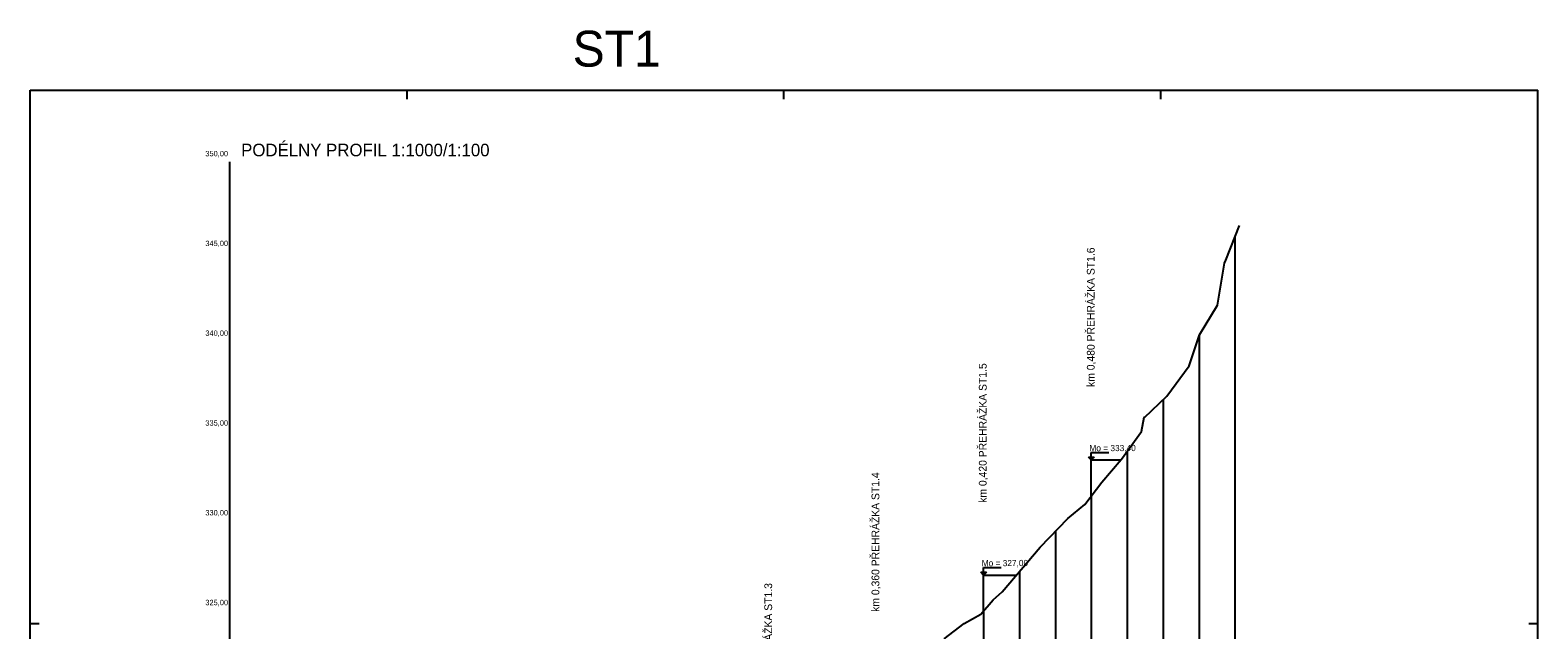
# Model space of a CAD drawing. Extents: x -500244 to -499404, y -1136557 to -1135632.
# Drawn here: x -500244 to -499404, y -1135966 to -1135632 of the extents above; entities that cross this region are included whole.
import ezdxf

# ---------------------------------------------------------------- set-up
doc = ezdxf.new("R2010")
doc.units = 0
for name, color, linetype in [('03_PC_NÁVRH_AS_H', 7, 'Continuous'), ('13', 7, 'Continuous'), ('28', 7, 'Continuous'), ('4', 7, 'Continuous'), ('56', 7, 'Continuous'), ('hraniceABH', 7, 'Continuous'), ('Vrstva 1', 7, 'Continuous'), ('Vrstva 4', 7, 'Continuous')]:
    doc.layers.add(name, color=color, linetype=linetype)

msp = doc.modelspace()

# ---------------------------------------------------------------- linework, layer by layer
for points in [[(-499734.44, -1135971.22), (-499723.25, -1135962.62), (-499723.22, -1135962.63), (-499714.02, -1135957.42), (-499714.02, -1135957.42), (-499707.14, -1135949.42), (-499707.14, -1135949.42), (-499702.11, -1135944.92), (-499702.11, -1135944.92), (-499702.11, -1135944.92), (-499694.61, -1135936.24), (-499680.87, -1135920.12), (-499680.87, -1135920.12), (-499665.52, -1135904.22), (-499665.52, -1135904.22), (-499656.1, -1135896.32), (-499656.1, -1135896.32), (-499646.62, -1135883.92), (-499646.62, -1135883.92), (-499646.61, -1135883.92), (-499635.77, -1135871.36), (-499635.66, -1135871), (-499624.55, -1135855.62), (-499624.55, -1135855.62), (-499623.08, -1135847.68), (-499622.93, -1135847.76), (-499622.8, -1135847.96), (-499622.79, -1135847.93), (-499610.45, -1135836.02), (-499610.45, -1135836.02), (-499597.89, -1135819.12), (-499597.89, -1135819.12), (-499592.27, -1135801.92), (-499592.27, -1135801.92), (-499582.12, -1135785.32), (-499582.12, -1135785.32), (-499578.28, -1135762.02), (-499577.46, -1135760.29), (-499569.89, -1135740.92)], [(-499572.45, -1135747.48), (-499572.45, -1136385.42), (-499572.45, -1136395.42), (-499572.45, -1136424.49)], [(-499592.45, -1135802.47), (-499592.45, -1136385.42), (-499592.45, -1136395.42), (-499592.45, -1136424.49)], [(-499612.45, -1135837.95), (-499612.45, -1136385.42), (-499612.45, -1136395.42), (-499612.45, -1136424.49)], [(-499632.45, -1135866.56), (-499632.45, -1136385.42), (-499632.45, -1136395.42), (-499632.45, -1136424.49)], [(-499652.45, -1135891.55), (-499652.45, -1136385.42), (-499652.45, -1136395.42), (-499652.45, -1136424.49)], [(-499672.45, -1135911.4), (-499672.45, -1136385.42), (-499672.45, -1136395.42), (-499672.45, -1136424.49)], [(-499692.45, -1135933.71), (-499692.45, -1136385.42), (-499692.45, -1136395.42), (-499692.45, -1136424.49)], [(-499712.45, -1135955.6), (-499712.45, -1136385.42), (-499712.45, -1136395.42), (-499712.45, -1136424.49)]]:
    msp.add_lwpolyline(points)
at = {"layer": '03_PC_NÁVRH_AS_H'}
for p, q in [((-499652.45, -1135871.55), (-499635.93, -1135871.55)), ((-499652.45, -1135891.55), (-499652.45, -1135871.55)), ((-499712.45, -1135935.6), (-499694.06, -1135935.6)), ((-499712.45, -1135955.6), (-499712.45, -1135935.6))]:
    msp.add_line(p, q, dxfattribs=at)
at = {"layer": '56'}
msp.add_line((-500132.45, -1136424.49), (-500132.45, -1135705.42), dxfattribs=at)
at = {"layer": 'hraniceABH'}
for p, q in [((-500243.68, -1135665.57), (-499403.68, -1135665.57)), ((-500243.68, -1136556.57), (-500243.68, -1135665.57)), ((-500033.68, -1135670.57), (-500033.68, -1135665.57)), ((-499823.68, -1135670.57), (-499823.68, -1135665.57)), ((-499613.68, -1135670.57), (-499613.68, -1135665.57)), ((-499403.68, -1136556.57), (-499403.68, -1135665.57)), ((-500243.68, -1135962.57), (-500238.68, -1135962.57)), ((-499408.68, -1135962.57), (-499403.68, -1135962.57))]:
    msp.add_line(p, q, dxfattribs=at)
at = {"layer": 'Vrstva 1'}
for p, q in [((-499652.45, -1135871.55), (-499654.07, -1135869.95)), ((-499654.07, -1135869.95), (-499650.87, -1135869.95)), ((-499652.47, -1135867.32), (-499642.77, -1135867.3)), ((-499652.45, -1135871.55), (-499652.47, -1135867.32)), ((-499712.47, -1135931.37), (-499702.77, -1135931.35)), ((-499712.45, -1135935.6), (-499712.47, -1135931.37)), ((-499712.45, -1135935.6), (-499714.07, -1135934)), ((-499714.07, -1135934), (-499710.87, -1135934))]:
    msp.add_line(p, q, dxfattribs=at)
at = {"layer": 'Vrstva 4'}
for p, q in [((-499650.87, -1135869.95), (-499652.45, -1135871.55)), ((-499710.87, -1135934), (-499712.45, -1135935.6))]:
    msp.add_line(p, q, dxfattribs=at)

# ---------------------------------------------------------------- texts
at = {"layer": '13'}
for s, p in [('350,00', (-500146.07, -1135702.42)), ('345,00', (-500146.07, -1135752.42)), ('340,00', (-500146.07, -1135802.42)), ('335,00', (-500146.07, -1135852.42)), ('330,00', (-500146.07, -1135902.42)), ('325,00', (-500146.07, -1135952.42))]:
    msp.add_text(s, height=3, dxfattribs=at).set_placement(p)
for s, p in [('km 0,480 PŘEHRÁŽKA ST1.6', (-499650.61, -1135830.87)), ('km 0,420 PŘEHRÁŽKA ST1.5', (-499710.79, -1135895.38)), ('km 0,360 PŘEHRÁŽKA ST1.4', (-499770.58, -1135956.11)), ('km 0,300 PŘEHRÁŽKA ST1.3', (-499830.29, -1136017.79))]:
    msp.add_text(s, height=4.32, rotation=90, dxfattribs=at).set_placement(p)
at = {"layer": '28'}
msp.add_text('ST1', height=20, dxfattribs=at).set_placement((-499941.43, -1135652.48))
at = {"layer": '4'}
msp.add_text('PODÉLNY PROFIL 1:1000/1:100', height=7, dxfattribs=at).set_placement((-500126.12, -1135702.42))
at = {"layer": 'Vrstva 1'}
for s, p in [('Mo = 333,40', (-499653.5, -1135866.65)), ('Mo = 327,00', (-499713.5, -1135930.7))]:
    msp.add_text(s, height=3.456, rotation=0.11931, dxfattribs=at).set_placement(p)

doc.saveas('drawing.dxf')
